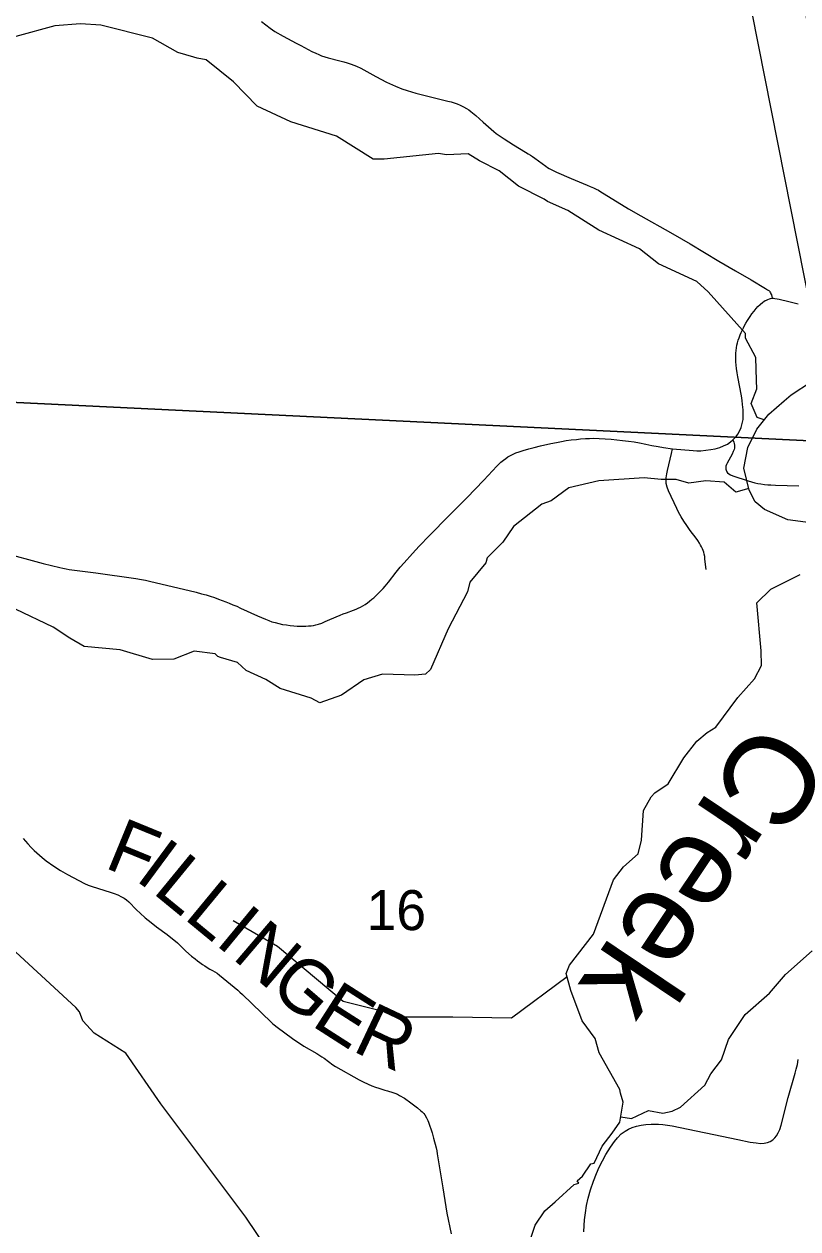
# Model space of a CAD drawing. Extents: x 0 to 34, y 0 to 22.
# Drawn here: x 26.308 to 27.118, y 17.66 to 18.921 of the extents above; entities that cross this region are included whole.
import ezdxf

# ---------------------------------------------------------------- set-up
doc = ezdxf.new("R2010")
doc.units = 0
for name, color, linetype in [('GM_X_County_Road', 7, 'Continuous'), ('GM_X_Minor_River', 7, 'Continuous'), ('GM_X_Minor_River_Text', 7, 'Continuous'), ('GM_X_Section', 7, 'Continuous'), ('GM_X_Section_Text', 7, 'Continuous'), ('GM_X_State_Route', 7, 'Continuous'), ('GM_X_Township_Road', 7, 'Continuous'), ('GM_X_Township_Road_Text', 7, 'Continuous'), ('SH_Text', 7, 'Continuous')]:
    doc.layers.add(name, color=color, linetype=linetype)

msp = doc.modelspace()

# ---------------------------------------------------------------- linework, layer by layer
at = {"layer": 'GM_X_County_Road'}
for points in [[(26.5568, 18.9237), (26.5658, 18.9167), (26.5706, 18.9133), (26.5794, 18.9085), (26.5929, 18.9012), (26.5978, 18.8985), (26.6055, 18.8944), (26.6095, 18.8925), (26.6137, 18.8906), (26.6168, 18.8892), (26.6197, 18.888), (26.6231, 18.8868), (26.6267, 18.8857), (26.6388, 18.8825), (26.6428, 18.8815), (26.6466, 18.8805), (26.6506, 18.8792), (26.6563, 18.8769), (26.6608, 18.8748), (26.6701, 18.8698), (26.6765, 18.8661), (26.6875, 18.8604), (26.6969, 18.856), (26.7036, 18.8532), (26.7092, 18.8514), (26.7139, 18.85), (26.7184, 18.8487), (26.7351, 18.8446), (26.752, 18.8404), (26.7552, 18.8396), (26.7585, 18.8386), (26.7617, 18.8375), (26.7648, 18.8362), (26.7684, 18.8344), (26.7713, 18.8327), (26.7737, 18.8312), (26.776, 18.8297), (26.7812, 18.8254), (26.789, 18.8183), (26.7973, 18.8109), (26.7999, 18.8087), (26.8026, 18.8066), (26.811, 18.8008), (26.8205, 18.7948), (26.8333, 18.787), (26.8359, 18.7854), (26.8383, 18.7839), (26.8406, 18.7824), (26.8429, 18.7807), (26.8544, 18.7724), (26.8563, 18.7711), (26.8581, 18.77), (26.8656, 18.7662), (26.881, 18.7595), (26.8979, 18.7526), (26.901, 18.7512), (26.9045, 18.7497), (26.907, 18.7484), (26.9096, 18.7471), (26.9122, 18.7455), (26.9154, 18.7435), (26.941, 18.7278), (26.9541, 18.7204), (26.985, 18.703), (26.9965, 18.6964), (27.0057, 18.6909), (27.0355, 18.673), (27.0529, 18.6626), (27.0694, 18.6533), (27.0846, 18.6444), (27.0867, 18.643), (27.0878, 18.6421), (27.0885, 18.6414), (27.089, 18.6407), (27.0897, 18.6396), (27.0901, 18.6386), (27.0906, 18.6375), (27.0916, 18.634)], [(26.2845, 18.3684), (26.3282, 18.3564), (26.3455, 18.3521), (26.3489, 18.3514), (26.3521, 18.3508), (26.3554, 18.3503), (26.3834, 18.3465), (26.4253, 18.3406), (26.4311, 18.3396), (26.4352, 18.3389), (26.4394, 18.3379), (26.4468, 18.3363), (26.4574, 18.3338), (26.4883, 18.3263), (26.4939, 18.3248), (26.4988, 18.3235), (26.503, 18.3222), (26.5075, 18.3207), (26.5118, 18.3192), (26.5154, 18.3178), (26.5193, 18.3163), (26.523, 18.3149), (26.5269, 18.3132), (26.5308, 18.3116), (26.5347, 18.3098), (26.5527, 18.3017), (26.5611, 18.298), (26.5644, 18.2967), (26.5677, 18.2955), (26.571, 18.2946), (26.5749, 18.2936), (26.5789, 18.2927), (26.5828, 18.2921), (26.5867, 18.2915), (26.5906, 18.2911), (26.5941, 18.2909), (26.5972, 18.2908), (26.6003, 18.2908), (26.6032, 18.2908), (26.6058, 18.291), (26.6086, 18.2913), (26.6111, 18.2916), (26.6138, 18.2922), (26.6166, 18.293), (26.6198, 18.294), (26.6235, 18.2956), (26.6283, 18.2977), (26.6391, 18.3023), (26.6423, 18.3036), (26.6457, 18.3048), (26.6531, 18.3075), (26.6557, 18.3085), (26.6581, 18.3097), (26.6603, 18.3108), (26.6628, 18.3121), (26.6652, 18.3136), (26.6676, 18.3153), (26.6699, 18.317), (26.6723, 18.3189), (26.6742, 18.3205), (26.6764, 18.3225), (26.6793, 18.3253), (26.6819, 18.328), (26.6841, 18.3303), (26.6863, 18.3328), (26.6897, 18.3369), (26.6978, 18.3472), (26.7021, 18.3524), (26.7062, 18.357), (26.7148, 18.3668), (26.722, 18.3745), (26.7326, 18.3856), (26.7529, 18.4062), (26.7719, 18.4252), (26.7897, 18.4438), (26.803, 18.4582), (26.8053, 18.4604), (26.8075, 18.4625), (26.8102, 18.4647), (26.8124, 18.4663), (26.8147, 18.4679), (26.8174, 18.4694), (26.8202, 18.4708), (26.8231, 18.4721), (26.8264, 18.4734), (26.8307, 18.4748), (26.8367, 18.4765), (26.8422, 18.478), (26.8489, 18.4796), (26.8596, 18.4819), (26.8657, 18.4831), (26.8707, 18.4841), (26.8759, 18.485), (26.8809, 18.4857), (26.8864, 18.4863), (26.8909, 18.4868), (26.896, 18.4871), (26.9002, 18.4874), (26.9047, 18.4875), (26.9103, 18.4873), (26.9167, 18.4869), (26.923, 18.4865), (26.9289, 18.4859), (26.9348, 18.4853), (26.941, 18.4845), (26.9471, 18.4836), (26.9526, 18.4826), (26.959, 18.4813), (26.9656, 18.4801), (26.9719, 18.4789), (26.9778, 18.4779), (26.9872, 18.4766), (27.0087, 18.4747), (27.0126, 18.4745), (27.0167, 18.4745), (27.022, 18.4749), (27.0272, 18.4756), (27.0319, 18.4766), (27.0365, 18.4779), (27.0405, 18.4795), (27.0446, 18.4815), (27.0479, 18.4838), (27.0503, 18.4858), (27.0536, 18.4893), (27.0555, 18.4918), (27.0574, 18.4951), (27.0589, 18.4986), (27.0602, 18.5029), (27.061, 18.5073), (27.0612, 18.5111), (27.061, 18.5172), (27.0605, 18.5227), (27.06, 18.5269), (27.0592, 18.532), (27.0554, 18.5518), (27.0547, 18.5559), (27.054, 18.5604), (27.0536, 18.5639), (27.0534, 18.5674), (27.0533, 18.5706), (27.0533, 18.5737), (27.0535, 18.5766), (27.0537, 18.5793), (27.0541, 18.5822), (27.0545, 18.5849), (27.0552, 18.5875), (27.056, 18.5901), (27.0568, 18.5927), (27.058, 18.5957), (27.0589, 18.5981), (27.0599, 18.6004), (27.0613, 18.603), (27.0626, 18.6055), (27.064, 18.608), (27.0655, 18.6107), (27.0683, 18.6151), (27.0702, 18.6177), (27.0725, 18.6207), (27.0746, 18.6233), (27.0765, 18.6255), (27.0788, 18.6276), (27.0815, 18.6299), (27.0828, 18.6308), (27.0842, 18.6316), (27.0854, 18.6322), (27.087, 18.6328), (27.0886, 18.6334), (27.0898, 18.6337), (27.0916, 18.634)], [(27.0916, 18.634), (27.093, 18.634), (27.0944, 18.6339), (27.0966, 18.6336), (27.0989, 18.6331), (27.1089, 18.6307), (27.1187, 18.6283)]]:
    msp.add_lwpolyline(points, dxfattribs=at)
at = {"layer": 'GM_X_Minor_River'}
for points in [[(27.0829, 18.5067), (27.0757, 18.5091), (27.0696, 18.5239), (27.0753, 18.5391), (27.0752, 18.5479), (27.0745, 18.5722), (27.0635, 18.5923), (27.0635, 18.5972), (27.0245, 18.6408), (27.0124, 18.6515), (26.9723, 18.67), (26.9526, 18.6859), (26.9099, 18.7052), (26.8774, 18.726), (26.8562, 18.7355), (26.8528, 18.7377), (26.8259, 18.7513), (26.8055, 18.7676), (26.7851, 18.7779), (26.773, 18.7854), (26.7503, 18.7842), (26.742, 18.7857), (26.6853, 18.7795), (26.6736, 18.7795), (26.6354, 18.8037), (26.5873, 18.8188), (26.5522, 18.8351), (26.5276, 18.8605), (26.4988, 18.8836), (26.4894, 18.8855), (26.486, 18.8866), (26.4693, 18.8915), (26.4425, 18.9062), (26.3884, 18.9198), (26.3672, 18.9213), (26.3404, 18.9193), (26.2996, 18.9082)], [(27.1449, 18.3971), (27.1079, 18.402), (27.0833, 18.413), (27.0738, 18.4209), (27.0674, 18.4331), (27.0617, 18.4562), (27.0659, 18.4779), (27.0753, 18.4969), (27.0878, 18.5129), (27.104, 18.5266), (27.1112, 18.5331), (27.1327, 18.5468)], [(27.067, 18.4348), (27.0534, 18.4311), (27.0413, 18.4414), (27.022, 18.4428), (27.0043, 18.4405), (26.991, 18.4443), (26.9752, 18.4442), (26.9574, 18.4461), (26.9098, 18.443), (26.8784, 18.4357), (26.8599, 18.4219), (26.8501, 18.4185), (26.8206, 18.3952), (26.8096, 18.3789), (26.793, 18.3625), (26.7915, 18.3572), (26.7749, 18.337), (26.7726, 18.3267), (26.7523, 18.2879), (26.7338, 18.2453), (26.7285, 18.2407), (26.7172, 18.2395), (26.6835, 18.2406), (26.6639, 18.2345), (26.6404, 18.2185), (26.6178, 18.2104), (26.6087, 18.2153), (26.5762, 18.2255), (26.5614, 18.235), (26.5406, 18.2444), (26.5315, 18.2528), (26.5138, 18.2581), (26.5111, 18.2592), (26.5081, 18.2618), (26.4862, 18.2645), (26.465, 18.2564), (26.4427, 18.256), (26.4087, 18.2662), (26.3712, 18.2695), (26.3561, 18.2782), (26.3387, 18.2899), (26.299, 18.3085)], [(26.9991, 18.153), (27.0125, 18.1703), (27.0234, 18.1795), (27.0325, 18.1852), (27.0555, 18.216), (27.0729, 18.2358), (27.0801, 18.2495), (27.08, 18.2651), (27.0755, 18.3153), (27.0902, 18.3297), (27.1208, 18.345)], [(26.8368, 17.6439), (26.8432, 17.6637), (26.8534, 17.6789), (26.8643, 17.6881), (26.884, 17.7064), (26.8889, 17.7079), (26.8874, 17.7102), (26.8927, 17.7151), (26.9017, 17.7281), (26.9051, 17.7288), (26.9134, 17.7463), (26.924, 17.76), (26.9319, 17.7715), (26.9353, 17.7924), (26.9327, 17.8019), (26.9319, 17.8057), (26.9103, 17.844), (26.9061, 17.8592), (26.8925, 17.8778), (26.8808, 17.9093), (26.8758, 17.9271), (26.8792, 17.9359), (26.9045, 17.9683), (26.9253, 18.0253), (26.9358, 18.039), (26.9513, 18.0524), (26.9547, 18.0668), (26.9566, 18.098), (26.9649, 18.1121), (26.9687, 18.1163), (26.9826, 18.1258), (26.9991, 18.153)], [(26.6717, 17.3353), (26.6812, 17.3584), (26.6822, 17.3762), (26.6747, 17.417), (26.664, 17.4496), (26.6499, 17.5215), (26.635, 17.5519), (26.6181, 17.5692), (26.6045, 17.5825), (26.5893, 17.6157), (26.5642, 17.637), (26.5403, 17.6723), (26.4513, 17.7909), (26.4148, 17.8437), (26.3814, 17.8649), (26.3697, 17.8778), (26.3662, 17.887), (26.3625, 17.8917), (26.2809, 17.9664), (26.2609, 18.0039)], [(26.8768, 17.9236), (26.8184, 17.8806), (26.7572, 17.8814), (26.7077, 17.8815), (26.6421, 17.898), (26.5735, 17.9556), (26.5271, 17.9825)], [(26.9329, 17.7773), (26.944, 17.7753), (26.9618, 17.7837), (26.9769, 17.7811), (26.9867, 17.783), (26.9954, 17.7872), (27.0211, 17.8104), (27.0271, 17.8222), (27.0385, 17.8367), (27.0456, 17.858), (27.063, 17.8843), (27.0887, 17.9067), (27.1053, 17.9262), (27.1332, 17.9509)]]:
    msp.add_lwpolyline(points, dxfattribs=at)
at = {"layer": 'GM_X_Section'}
for points in [[(26.2655, 19.5533), (27.3196, 19.501), (27.254, 18.479), (26.2062, 18.5294)], [(26.2062, 18.5294), (27.254, 18.479), (27.228, 18.0601), (27.2029, 17.6387), (27.1952, 17.4804), (26.5953, 17.5088), (26.1481, 17.5351), (26.1482, 17.5386), (26.1578, 17.7173), (26.1806, 18.1307)]]:
    msp.add_lwpolyline(points, close=True, dxfattribs=at)
at = {"layer": 'GM_X_State_Route'}
msp.add_lwpolyline([(26.8942, 17.6567), (26.8945, 17.6634), (26.895, 17.6695), (26.896, 17.6768), (26.8971, 17.6843), (26.8988, 17.6921), (26.9012, 17.7006), (26.9044, 17.7099), (26.9076, 17.718), (26.9104, 17.7244), (26.9137, 17.731), (26.9172, 17.7376), (26.922, 17.7454), (26.9262, 17.7513), (26.9296, 17.7553), (26.9335, 17.7593), (26.9374, 17.7623), (26.9409, 17.7644), (26.945, 17.766), (26.9495, 17.7673), (26.9544, 17.7684), (26.9592, 17.7691), (26.9646, 17.7695), (26.9681, 17.7696), (26.9723, 17.7695), (26.977, 17.769), (26.9818, 17.7684), (26.9867, 17.7676), (27.0556, 17.7533), (27.0684, 17.7508), (27.0746, 17.7498), (27.0792, 17.7493), (27.0831, 17.7495), (27.0865, 17.7502), (27.0895, 17.7513), (27.0922, 17.753), (27.0944, 17.7552), (27.0961, 17.7573), (27.0978, 17.7603), (27.0994, 17.764), (27.1008, 17.7684), (27.1082, 17.7973), (27.1156, 17.8229), (27.1167, 17.827), (27.1178, 17.8319), (27.1188, 17.8373)], dxfattribs=at)
at = {"layer": 'GM_X_Township_Road'}
for points in [[(27.0224, 18.35), (27.0211, 18.361), (27.0208, 18.3636), (27.0204, 18.3662), (27.0199, 18.3681), (27.0192, 18.3701), (27.0185, 18.3719), (27.0176, 18.3738), (27.0165, 18.3757), (27.0152, 18.3778), (27.0136, 18.3806), (27.0117, 18.3831), (27.0056, 18.3911), (27.002, 18.3961), (26.9989, 18.4007), (26.9962, 18.4051), (26.9934, 18.41), (26.9915, 18.4139), (26.983, 18.4324), (26.9815, 18.4363), (26.9806, 18.44), (26.9803, 18.4431), (26.9804, 18.4462), (26.981, 18.4501), (26.9817, 18.4539), (26.9859, 18.4715), (26.9872, 18.4766)], [(27.0503, 18.4858), (27.0512, 18.4833), (27.0516, 18.4819), (27.0519, 18.4803), (27.052, 18.4787), (27.0519, 18.4773), (27.0515, 18.4759), (27.0507, 18.4735), (27.0495, 18.4709), (27.0444, 18.4616), (27.0436, 18.46), (27.043, 18.4583), (27.0429, 18.4565), (27.0429, 18.4553), (27.0431, 18.454), (27.0438, 18.4525), (27.0447, 18.4512), (27.046, 18.4501), (27.0478, 18.4491), (27.0502, 18.4481), (27.0662, 18.4428), (27.0697, 18.4418), (27.0734, 18.4409), (27.0763, 18.4402), (27.0795, 18.4397), (27.0834, 18.4392), (27.0868, 18.4388), (27.0899, 18.4386), (27.095, 18.4384), (27.1193, 18.4377)], [(26.3073, 18.0686), (26.3121, 18.0629), (26.3155, 18.0592), (26.3187, 18.0559), (26.327, 18.0488), (26.3313, 18.0453), (26.3394, 18.0396), (26.3463, 18.0351), (26.3536, 18.0307), (26.3714, 18.0215), (26.3754, 18.0197), (26.3795, 18.0182), (26.3982, 18.0124), (26.4026, 18.011), (26.4063, 18.0095), (26.4102, 18.0076), (26.4129, 18.0061), (26.4153, 18.0043), (26.4178, 18.0021), (26.4258, 17.9939), (26.4298, 17.9903), (26.4351, 17.9855), (26.4411, 17.9806), (26.4467, 17.9761), (26.458, 17.968), (26.4687, 17.9593), (26.4776, 17.9507), (26.4836, 17.9454), (26.4872, 17.9425), (26.4896, 17.9406), (26.4922, 17.9387), (26.4949, 17.9368), (26.4973, 17.9352), (26.4998, 17.9336), (26.5028, 17.9318), (26.5055, 17.9304), (26.508, 17.9289), (26.5102, 17.9274), (26.5129, 17.9254), (26.5243, 17.916), (26.5318, 17.9098), (26.5341, 17.9078), (26.537, 17.9051), (26.5669, 17.8762), (26.5683, 17.8749), (26.5701, 17.8734), (26.573, 17.871), (26.5892, 17.8592), (26.6012, 17.8513), (26.6146, 17.8433), (26.6178, 17.8414), (26.6198, 17.8401), (26.6222, 17.8386), (26.6315, 17.8316), (26.6343, 17.8298), (26.659, 17.816), (26.6632, 17.8139), (26.6683, 17.8115), (26.6724, 17.8098), (26.6761, 17.8083), (26.6795, 17.8072), (26.6826, 17.8062), (26.6858, 17.8051), (26.6887, 17.8043), (26.6942, 17.8026), (26.6965, 17.8018), (26.699, 17.8008), (26.7014, 17.7996), (26.7063, 17.7968), (26.7132, 17.7918), (26.72, 17.7865), (26.7236, 17.7835), (26.7248, 17.7825), (26.7259, 17.7815), (26.7268, 17.7805), (26.7277, 17.7792), (26.7295, 17.7762), (26.7302, 17.7749), (26.7309, 17.7734), (26.7316, 17.7716), (26.7354, 17.7604), (26.7362, 17.7576), (26.737, 17.7548), (26.7395, 17.7446), (26.7402, 17.7415), (26.7407, 17.7384), (26.7466, 17.7027), (26.7509, 17.6762), (26.7553, 17.6548)]]:
    msp.add_lwpolyline(points, dxfattribs=at)
at = {"layer": 'SH_Text'}
msp.add_lwpolyline([(27.0492, 19.0391), (27.2621, 17.9634), (27.0492, 19.4888)], close=True, dxfattribs=at)

# ---------------------------------------------------------------- texts
at = {"layer": 'GM_X_Minor_River_Text'}
msp.add_text('Creek', height=0.09469, rotation=236.1304, dxfattribs=at).set_placement((27.0759, 18.1964))
at = {"layer": 'GM_X_Section_Text'}
msp.add_text('16', height=0.04186, rotation=0, dxfattribs=at).set_placement((26.6668, 17.9726))
at = {"layer": 'GM_X_Township_Road_Text'}
for s, rotation, p in [('F', 337.6802, (26.391, 18.0386)), ('I', 323.4986, (26.4232, 18.0258)), ('L', 320.6334, (26.4414, 18.0124)), ('L', 320.4721, (26.4742, 17.9855)), ('I', 320.4393, (26.507, 17.9585)), ('N', 319.5629, (26.5248, 17.9437)), ('G', 319.276, (26.5628, 17.9114)), ('E', 327.3764, (26.6077, 17.8735)), ('R', 334.7222, (26.6505, 17.8467))]:
    msp.add_text(s, height=0.0568, rotation=rotation, dxfattribs=at).set_placement(p)

doc.saveas('drawing.dxf')
